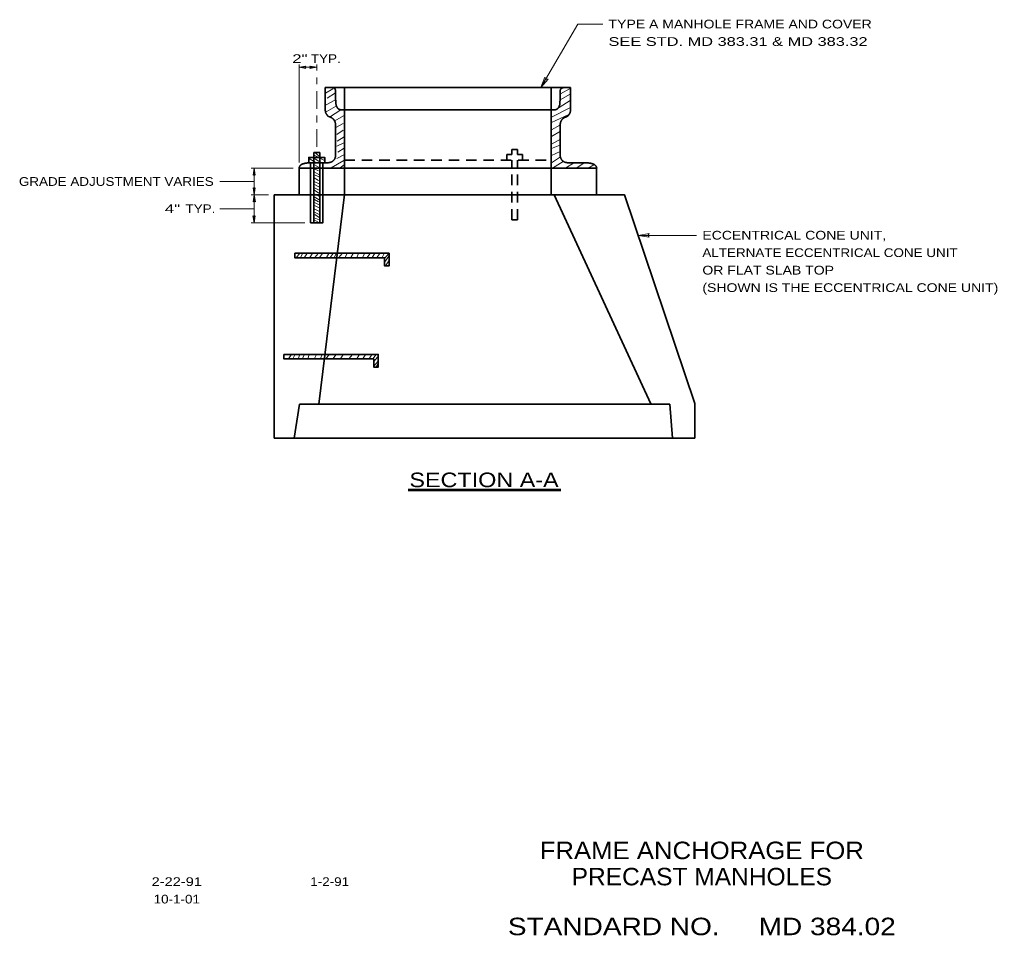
# Model space of a CAD drawing. Extents: x 21 to 35.7, y -17 to 3.5.
# Drawn here: x 21.5 to 35.74, y -17.04 to -3.71 of the extents above; entities that cross this region are included whole.
import ezdxf
from ezdxf.enums import TextEntityAlignment as Align

# ---------------------------------------------------------------- set-up
doc = ezdxf.new("R2010")
doc.units = 0
doc.header["$LTSCALE"] = 0.051
for name, pattern in [('DOT_DASHED', [7.7, 5, -1.2, 0.3, -1.2]), ('DOTTED', [1.5, 0.3, -1.2]), ('MEDIUM_DASHED', [4.5, 3, -1.5])]:
    doc.linetypes.add(name, pattern=pattern)
for name, color, linetype, lineweight in [('1', 7, 'Continuous', 35), ('10', 7, 'Continuous', 13), ('12', 7, 'Continuous', 53), ('6', 7, 'DOTTED', 13)]:
    doc.layers.add(name, color=color, linetype=linetype, lineweight=lineweight)
doc.layers.add('13', color=7, linetype='Continuous')

msp = doc.modelspace()

# ---------------------------------------------------------------- linework, layer by layer
at = {"layer": '1'}
for p, q in [((25.9515, -4.69192), (29.52275, -4.69192)), ((25.9515, -4.69192), (25.9515, -4.99533)), ((26.23083, -6.25367), (26.23083, -4.69192)), ((29.24342, -6.25367), (29.24342, -4.69192)), ((29.52275, -4.69192), (29.52275, -4.99533)), ((26.18608, -5.01858), (29.28817, -5.01858)), ((26.10133, -5.67925), (26.10133, -5.27792)), ((29.37292, -5.67925), (29.37292, -5.27792)), ((25.78383, -6.66225), (25.78383, -5.64075)), ((25.87033, -5.64075), (25.78383, -5.64075)), ((25.69417, -5.79242), (25.94292, -5.79242)), ((25.73592, -6.66225), (25.73592, -5.79283)), ((29.78008, -5.79242), (29.53133, -5.79242)), ((25.5695, -5.86875), (25.5695, -6.25517)), ((25.5695, -5.86875), (29.9025, -5.86875)), ((25.56725, -6.10233), (25.5695, -6.10192)), ((25.20825, -9.79667), (25.20825, -6.25617)), ((26.23083, -6.25367), (25.85725, -9.30125)), ((30.691, -9.296), (29.28475, -6.25458)), ((25.499, -9.79667), (25.57425, -9.305)), ((25.57425, -9.305), (30.97125, -9.30433)), ((30.97125, -9.30433), (31.00867, -9.79667)), ((31.33242, -9.79667), (31.33242, -9.293)), ((25.20825, -9.79667), (31.33242, -9.79667))]:
    msp.add_line(p, q, dxfattribs=at)
for points in [[(25.87658, -6.66225), (25.87033, -6.66225), (25.87033, -5.64075)], [(25.71125, -5.79242), (25.71125, -5.71292), (25.94292, -5.71292), (25.94292, -5.79242)], [(25.73592, -6.66225), (25.91825, -6.66225), (25.91825, -5.79458)], [(31.33058, -9.29358), (30.31017, -6.25675), (25.20825, -6.25617)]]:
    msp.add_lwpolyline(points, dxfattribs=at)
for points in [[(25.5085, -7.10775), (26.88042, -7.10775), (26.88042, -7.29117), (26.81633, -7.29117), (26.81633, -7.17167), (25.5085, -7.17167)], [(25.35058, -8.57967), (26.7225, -8.57967), (26.7225, -8.76308), (26.65842, -8.76308), (26.65842, -8.64358), (25.35058, -8.64358)]]:
    msp.add_lwpolyline(points, close=True, dxfattribs=at)
for points in [[(26.03483, -4.69192), (26.04558, -4.69433), (26.05317, -4.69575), (26.06225, -4.6975), (26.06933, -4.69942), (26.07533, -4.70158), (26.07925, -4.70342), (26.08267, -4.70533), (26.08617, -4.7075), (26.08908, -4.70992), (26.09175, -4.71275), (26.09392, -4.7155), (26.09542, -4.71842), (26.097, -4.7225), (26.09808, -4.7265), (26.09942, -4.73033), (26.10075, -4.73642), (26.102, -4.74725), (26.10225, -4.75067), (26.10225, -4.752), (26.10225, -4.75358), (26.10225, -4.75667), (26.10225, -4.76025), (26.10233, -4.76475), (26.10242, -4.76917), (26.10225, -4.774), (26.10225, -4.77742), (26.10208, -4.78208), (26.10208, -4.78383), (26.10225, -4.79117), (26.10242, -4.79633), (26.1025, -4.80042), (26.1025, -4.80867), (26.10258, -4.81925), (26.10258, -4.82783), (26.10275, -4.83442), (26.10258, -4.84308), (26.10225, -4.84958), (26.10258, -4.86658), (26.10292, -4.87717), (26.104, -4.8845), (26.1045, -4.89008), (26.10517, -4.89542), (26.10567, -4.90083), (26.1065, -4.90842), (26.10658, -4.91133), (26.10658, -4.91442), (26.10683, -4.92633), (26.10717, -4.93442), (26.10817, -4.94133), (26.11033, -4.94925), (26.11125, -4.95175), (26.11233, -4.95558), (26.11467, -4.96317), (26.11733, -4.96917), (26.119, -4.974), (26.12008, -4.978), (26.12217, -4.981), (26.12317, -4.98367), (26.12533, -4.98592), (26.12742, -4.98883), (26.1285, -4.99083), (26.13058, -4.99275), (26.13258, -4.99475), (26.13575, -4.99967), (26.13775, -5.00133), (26.13992, -5.00358), (26.14208, -5.00492), (26.14408, -5.00617), (26.14717, -5.00842), (26.14942, -5.00967), (26.15183, -5.01042), (26.15433, -5.01108), (26.15817, -5.013), (26.16042, -5.01383), (26.16217, -5.01458), (26.16567, -5.016), (26.16867, -5.01692), (26.17075, -5.01792), (26.17483, -5.01883), (26.18608, -5.01858)], [(29.43942, -4.69192), (29.42867, -4.69433), (29.42108, -4.69575), (29.412, -4.6975), (29.40492, -4.69942), (29.39892, -4.70158), (29.395, -4.70342), (29.39158, -4.70533), (29.38808, -4.7075), (29.38517, -4.70992), (29.3825, -4.71275), (29.38033, -4.7155), (29.37883, -4.71842), (29.37725, -4.7225), (29.37617, -4.7265), (29.37483, -4.73033), (29.3735, -4.73642), (29.37225, -4.74725), (29.372, -4.75067), (29.372, -4.752), (29.372, -4.75358), (29.372, -4.75667), (29.372, -4.76025), (29.37192, -4.76475), (29.37183, -4.76917), (29.372, -4.774), (29.372, -4.77742), (29.37217, -4.78208), (29.37217, -4.78383), (29.372, -4.79117), (29.37183, -4.79633), (29.37175, -4.80042), (29.37175, -4.80867), (29.37167, -4.81925), (29.37167, -4.82783), (29.3715, -4.83442), (29.37167, -4.84308), (29.372, -4.84958), (29.37167, -4.86658), (29.37133, -4.87717), (29.37025, -4.8845), (29.36975, -4.89008), (29.36908, -4.89542), (29.36858, -4.90083), (29.36775, -4.90842), (29.36767, -4.91133), (29.36767, -4.91442), (29.36742, -4.92633), (29.36708, -4.93442), (29.36608, -4.94133), (29.36392, -4.94925), (29.363, -4.95175), (29.36192, -4.95558), (29.35958, -4.96317), (29.35692, -4.96917), (29.35525, -4.974), (29.35417, -4.978), (29.35208, -4.981), (29.35108, -4.98367), (29.34892, -4.98592), (29.34683, -4.98883), (29.34575, -4.99083), (29.34367, -4.99275), (29.34167, -4.99475), (29.3385, -4.99967), (29.3365, -5.00133), (29.33433, -5.00358), (29.33217, -5.00492), (29.33017, -5.00617), (29.32708, -5.00842), (29.32483, -5.00967), (29.32242, -5.01042), (29.31992, -5.01108), (29.31608, -5.013), (29.31383, -5.01383), (29.31208, -5.01458), (29.30858, -5.016), (29.30558, -5.01692), (29.3035, -5.01792), (29.29942, -5.01883), (29.28817, -5.01858)], [(25.9515, -4.99533), (25.9515, -5.00208), (25.9515, -5.01008), (25.95117, -5.01333), (25.95183, -5.01925), (25.952, -5.03108), (25.95283, -5.03542), (25.9535, -5.04225), (25.95433, -5.046), (25.9545, -5.04833), (25.95533, -5.05117), (25.95533, -5.0525), (25.95567, -5.05383), (25.95617, -5.0555), (25.95683, -5.05783), (25.958, -5.06133), (25.95967, -5.0645), (25.96133, -5.06667), (25.96233, -5.06917), (25.9635, -5.07133), (25.96433, -5.07367), (25.96533, -5.07533), (25.96717, -5.0785), (25.96933, -5.08167), (25.9725, -5.08617), (25.97417, -5.08883), (25.97633, -5.09233), (25.979, -5.09567), (25.98067, -5.09917), (25.98392, -5.10208), (25.98625, -5.10425), (25.98825, -5.10625), (25.99125, -5.10942), (25.99542, -5.11292), (26.00158, -5.11642), (26.00742, -5.11908), (26.01342, -5.12125), (26.01892, -5.12342), (26.02225, -5.12458), (26.02533, -5.12567), (26.02658, -5.12608), (26.02833, -5.12667), (26.03742, -5.13117), (26.04108, -5.133), (26.0465, -5.13592), (26.05283, -5.14058), (26.05975, -5.14575), (26.0625, -5.14817), (26.06567, -5.151), (26.06883, -5.15417), (26.07075, -5.15633), (26.07292, -5.15892), (26.07508, -5.16133), (26.07742, -5.16475), (26.08058, -5.16883), (26.08267, -5.172), (26.08442, -5.17467), (26.08558, -5.177), (26.08758, -5.18025), (26.08925, -5.18383), (26.091, -5.18733), (26.09375, -5.194), (26.09608, -5.20083), (26.09725, -5.20508), (26.09817, -5.20858), (26.09892, -5.214), (26.09983, -5.21917), (26.10067, -5.22358), (26.10125, -5.22967), (26.10117, -5.23683), (26.10067, -5.24517), (26.10067, -5.25483), (26.10092, -5.26225), (26.10117, -5.27275), (26.10117, -5.27708), (26.10133, -5.27792)], [(29.52275, -4.99533), (29.52275, -5.00208), (29.52275, -5.01008), (29.52308, -5.01333), (29.52242, -5.01925), (29.52225, -5.03108), (29.52142, -5.03542), (29.52075, -5.04225), (29.51992, -5.046), (29.51975, -5.04833), (29.51892, -5.05117), (29.51892, -5.0525), (29.51858, -5.05383), (29.51808, -5.0555), (29.51742, -5.05783), (29.51625, -5.06133), (29.51458, -5.0645), (29.51292, -5.06667), (29.51192, -5.06917), (29.51075, -5.07133), (29.50992, -5.07367), (29.50892, -5.07533), (29.50708, -5.0785), (29.50492, -5.08167), (29.50175, -5.08617), (29.50008, -5.08883), (29.49792, -5.09233), (29.49525, -5.09567), (29.49358, -5.09917), (29.49033, -5.10208), (29.488, -5.10425), (29.486, -5.10625), (29.483, -5.10942), (29.47883, -5.11292), (29.47267, -5.11642), (29.46683, -5.11908), (29.46083, -5.12125), (29.45533, -5.12342), (29.452, -5.12458), (29.44892, -5.12567), (29.44767, -5.12608), (29.44592, -5.12667), (29.43683, -5.13117), (29.43317, -5.133), (29.42775, -5.13592), (29.42142, -5.14058), (29.4145, -5.14575), (29.41175, -5.14817), (29.40858, -5.151), (29.40542, -5.15417), (29.4035, -5.15633), (29.40133, -5.15892), (29.39917, -5.16133), (29.39683, -5.16475), (29.39367, -5.16883), (29.39158, -5.172), (29.38983, -5.17467), (29.38867, -5.177), (29.38667, -5.18025), (29.385, -5.18383), (29.38325, -5.18733), (29.3805, -5.194), (29.37817, -5.20083), (29.377, -5.20508), (29.37608, -5.20858), (29.37533, -5.214), (29.37442, -5.21917), (29.37358, -5.22358), (29.373, -5.22967), (29.37308, -5.23683), (29.37358, -5.24517), (29.37358, -5.25483), (29.37333, -5.26225), (29.37308, -5.27275), (29.37308, -5.27708), (29.37292, -5.27792)], [(26.10133, -5.67925), (26.10158, -5.68442), (26.10108, -5.69167), (26.10067, -5.698), (26.09833, -5.70783), (26.09692, -5.71292), (26.09558, -5.71733), (26.094, -5.72242), (26.091, -5.72892), (26.08767, -5.73558), (26.08192, -5.74425), (26.07717, -5.75025), (26.07075, -5.75725), (26.0655, -5.76183), (26.05933, -5.76692), (26.05075, -5.77233), (26.04475, -5.77567), (26.03933, -5.77883), (26.03267, -5.78125), (26.02933, -5.78217), (26.02517, -5.78358), (26.01992, -5.78517), (26.01625, -5.78583), (26.01358, -5.786), (26.00958, -5.78708), (26.00533, -5.78758), (26.00083, -5.78825), (25.99667, -5.78933), (25.99208, -5.7895), (25.98825, -5.78983), (25.98475, -5.79042), (25.98092, -5.79058), (25.97617, -5.79092), (25.97225, -5.79133), (25.96858, -5.79217), (25.96442, -5.79233), (25.95875, -5.79233), (25.95275, -5.7925), (25.94825, -5.7925), (25.94292, -5.79242)], [(29.37292, -5.67925), (29.37267, -5.68442), (29.37317, -5.69167), (29.37358, -5.698), (29.37592, -5.70783), (29.37733, -5.71292), (29.37867, -5.71733), (29.38025, -5.72242), (29.38325, -5.72892), (29.38658, -5.73558), (29.39233, -5.74425), (29.39708, -5.75025), (29.4035, -5.75725), (29.40875, -5.76183), (29.41492, -5.76692), (29.4235, -5.77233), (29.4295, -5.77567), (29.43492, -5.77883), (29.44158, -5.78125), (29.44492, -5.78217), (29.44908, -5.78358), (29.45433, -5.78517), (29.458, -5.78583), (29.46067, -5.786), (29.46467, -5.78708), (29.46892, -5.78758), (29.47342, -5.78825), (29.47758, -5.78933), (29.48217, -5.7895), (29.486, -5.78983), (29.4895, -5.79042), (29.49333, -5.79058), (29.49808, -5.79092), (29.502, -5.79133), (29.50567, -5.79217), (29.50983, -5.79233), (29.5155, -5.79233), (29.5215, -5.7925), (29.526, -5.7925), (29.53133, -5.79242)], [(25.69417, -5.79242), (25.6915, -5.7925), (25.68492, -5.79342), (25.67808, -5.79442), (25.66517, -5.79608), (25.65858, -5.79717), (25.65358, -5.798), (25.64792, -5.79908), (25.64492, -5.8), (25.64258, -5.801), (25.63917, -5.80225), (25.63617, -5.80292), (25.63392, -5.8035), (25.63208, -5.80417), (25.62925, -5.80475), (25.62683, -5.80558), (25.62375, -5.80658), (25.62017, -5.80725), (25.61675, -5.80858), (25.61358, -5.80975), (25.61083, -5.81142), (25.60867, -5.81258), (25.60633, -5.81367), (25.60292, -5.8155), (25.60075, -5.81767), (25.598, -5.81942), (25.59608, -5.82092), (25.59475, -5.82225), (25.59192, -5.82542), (25.58892, -5.82792), (25.58642, -5.8305), (25.58017, -5.83867), (25.57667, -5.84475), (25.57483, -5.84917), (25.57358, -5.85308), (25.57242, -5.85708), (25.57108, -5.86158), (25.5695, -5.86875)], [(29.78008, -5.79242), (29.78275, -5.7925), (29.78933, -5.79342), (29.79617, -5.79442), (29.80908, -5.79608), (29.81567, -5.79717), (29.82067, -5.798), (29.82633, -5.79908), (29.82933, -5.8), (29.83167, -5.801), (29.83508, -5.80225), (29.83808, -5.80292), (29.84033, -5.8035), (29.84217, -5.80417), (29.845, -5.80475), (29.84742, -5.80558), (29.8505, -5.80658), (29.85408, -5.80725), (29.8575, -5.80858), (29.86067, -5.80975), (29.86342, -5.81142), (29.86558, -5.81258), (29.86792, -5.81367), (29.87133, -5.8155), (29.8735, -5.81767), (29.87625, -5.81942), (29.87817, -5.82092), (29.8795, -5.82225), (29.88233, -5.82542), (29.88533, -5.82792), (29.88783, -5.8305), (29.89408, -5.83867), (29.89758, -5.84475), (29.89942, -5.84917), (29.90067, -5.85308), (29.90183, -5.85708), (29.90317, -5.86158), (29.90475, -5.86875)]]:
    msp.add_spline(points, degree=3, dxfattribs=at)
at = {"layer": '10'}
for p, q in [((29.0925, -4.69642), (29.62708, -3.77083)), ((29.62708, -3.77083), (29.99283, -3.77083)), ((25.5695, -5.78542), (25.5695, -4.35858)), ((25.66933, -4.3825), (25.5695, -4.40025)), ((25.66967, -4.41583), (25.5695, -4.40025)), ((25.5695, -4.40025), (25.82708, -4.40025)), ((25.66933, -4.3825), (25.657, -4.39933)), ((25.66967, -4.41583), (25.657, -4.39933)), ((25.72692, -4.38467), (25.82708, -4.40025)), ((25.72692, -4.38467), (25.73958, -4.40117)), ((25.72725, -4.418), (25.82708, -4.40025)), ((25.72725, -4.418), (25.73958, -4.40117)), ((29.14942, -4.5445), (29.0925, -4.69642)), ((29.14942, -4.5445), (29.1625, -4.57517)), ((29.19558, -4.57117), (29.0925, -4.69642)), ((29.19558, -4.57117), (29.1625, -4.57517)), ((25.48617, -5.86875), (24.87492, -5.86875)), ((24.89992, -5.96875), (24.91658, -5.86875)), ((24.89992, -5.96875), (24.91658, -5.95625)), ((24.93325, -5.96875), (24.91658, -5.86875)), ((24.91658, -6.25617), (24.91658, -5.86875)), ((24.93325, -5.96875), (24.91658, -5.95625)), ((24.91658, -6.0625), (24.41658, -6.0625)), ((25.12492, -6.25617), (24.87492, -6.25617)), ((24.89992, -6.15617), (24.91658, -6.25617)), ((24.89992, -6.15617), (24.91658, -6.16867)), ((24.90133, -6.35642), (24.91658, -6.25617)), ((24.93325, -6.15617), (24.91658, -6.25617)), ((24.93325, -6.15617), (24.91658, -6.16867)), ((24.93467, -6.35592), (24.91658, -6.25617)), ((24.91658, -6.25617), (24.91658, -6.66225)), ((24.90133, -6.35642), (24.91783, -6.34367)), ((24.93467, -6.35592), (24.91783, -6.34367)), ((24.91658, -6.45917), (24.41658, -6.45917)), ((25.65258, -6.66225), (24.87492, -6.66225)), ((24.8985, -6.5625), (24.91658, -6.66225)), ((24.8985, -6.5625), (24.91533, -6.57475)), ((24.93183, -6.562), (24.91533, -6.57475)), ((24.93183, -6.562), (24.91658, -6.66225)), ((30.66817, -6.81908), (30.50825, -6.84617)), ((30.66817, -6.81908), (30.64825, -6.84583)), ((30.66833, -6.87242), (30.50825, -6.84617)), ((30.50825, -6.84617), (31.3595, -6.84617)), ((30.66833, -6.87242), (30.64825, -6.84583))]:
    msp.add_line(p, q, dxfattribs=at)
at = {"layer": '10', "linetype": 'DOT_DASHED'}
msp.add_line((25.82708, -5.55742), (25.82708, -4.35858), dxfattribs=at)
at = {"layer": '10', "linetype": 'MEDIUM_DASHED', "lineweight": 35}
for p, q in [((28.59383, -5.75042), (28.59383, -5.67092)), ((28.59383, -5.67092), (28.66642, -5.67092)), ((28.75292, -5.59875), (28.66642, -5.59875)), ((28.66642, -5.67092), (28.66642, -5.59875)), ((28.75292, -5.67092), (28.75292, -5.59875)), ((28.75292, -5.67092), (28.8255, -5.67092)), ((28.8255, -5.67092), (28.8255, -5.75042)), ((26.23083, -5.75042), (29.24342, -5.75042)), ((28.66642, -6.62025), (28.66642, -5.75042)), ((28.75292, -6.62025), (28.75292, -5.75042)), ((28.66642, -6.62025), (28.75292, -6.62025))]:
    msp.add_line(p, q, dxfattribs=at)
at = {"layer": '10', "lineweight": 35}
msp.add_line((29.9025, -5.86875), (29.9025, -6.25675), dxfattribs=at)
at = {"layer": '12'}
msp.add_line((27.15758, -10.5505), (29.38308, -10.5505), dxfattribs=at)
at = {"layer": '6', "linetype": 'Continuous'}
for p, q in [((25.95417, -4.77767), (26.05992, -4.71567)), ((26.10175, -4.77275), (25.977, -4.85008)), ((29.37242, -4.875), (29.5175, -4.79225)), ((29.51892, -4.70833), (29.37517, -4.7885)), ((26.09158, -4.87775), (25.96367, -4.94725)), ((25.96667, -5.049), (26.10258, -4.97033)), ((29.24575, -5.12767), (29.52233, -4.98283)), ((29.51975, -4.88275), (29.356, -4.98517)), ((26.16483, -5.029), (26.02908, -5.11567)), ((26.09042, -5.17825), (26.21725, -5.10483)), ((29.49892, -5.08767), (29.24792, -5.20133)), ((26.21442, -5.21667), (26.11667, -5.27058)), ((29.24658, -5.30817), (29.36842, -5.24)), ((26.11883, -5.37742), (26.21433, -5.3145)), ((29.37742, -5.33025), (29.2475, -5.4055)), ((26.11908, -5.54708), (26.23008, -5.49292)), ((26.22642, -5.41417), (26.12475, -5.47408)), ((29.36567, -5.53208), (29.24617, -5.58308)), ((29.24792, -5.51825), (29.37767, -5.446)), ((25.7885, -5.67708), (25.93883, -5.759)), ((25.8, -5.64092), (25.86825, -5.69783)), ((26.12058, -5.72675), (26.22242, -5.67175)), ((26.22558, -5.57692), (26.13417, -5.63767)), ((29.24783, -5.68275), (29.372, -5.62383)), ((25.71517, -5.72733), (25.81758, -5.78875)), ((25.78642, -5.724), (25.89725, -5.78908)), ((25.79442, -5.81767), (25.86142, -5.85733)), ((26.03675, -5.86125), (26.22, -5.75567)), ((26.22733, -5.82042), (26.16708, -5.86258)), ((29.37867, -5.70358), (29.24592, -5.78933)), ((29.26142, -5.86725), (29.41575, -5.77225)), ((29.45625, -5.86575), (29.56775, -5.795)), ((29.606, -5.86867), (29.718, -5.79525)), ((29.77908, -5.86817), (29.86392, -5.81892)), ((25.78225, -5.87483), (25.85317, -5.90642)), ((25.78608, -5.96258), (25.85808, -5.99608)), ((25.78933, -5.92358), (25.85733, -5.96017)), ((25.788, -6.00842), (25.85392, -6.04608)), ((25.793, -6.10517), (25.85783, -6.13783)), ((25.80033, -6.06508), (25.861, -6.09492)), ((25.79258, -6.188), (25.85975, -6.23367)), ((25.795, -6.153), (25.86292, -6.18667)), ((25.79675, -6.24283), (25.85958, -6.27758)), ((25.79158, -6.28783), (25.86158, -6.32742)), ((25.79417, -6.36867), (25.86417, -6.40425)), ((25.79433, -6.32575), (25.85508, -6.3585)), ((25.79508, -6.41258), (25.862, -6.44717)), ((25.79592, -6.50633), (25.86383, -6.541)), ((25.79875, -6.54425), (25.86267, -6.58492)), ((25.80117, -6.46433), (25.85992, -6.49517)), ((25.788, -6.61833), (25.86008, -6.65983)), ((25.7895, -6.59133), (25.86342, -6.61983)), ((25.52608, -7.17233), (25.57975, -7.10742)), ((25.59025, -7.17008), (25.62567, -7.1075)), ((25.64525, -7.171), (25.6845, -7.113)), ((25.72783, -7.17042), (25.75958, -7.11267)), ((25.80183, -7.16933), (25.84875, -7.10925)), ((25.8655, -7.16967), (25.91075, -7.1105)), ((25.96967, -7.17042), (26.00292, -7.1125)), ((26.02333, -7.16817), (26.06775, -7.11)), ((26.07925, -7.16975), (26.11033, -7.11358)), ((26.15092, -7.16842), (26.19583, -7.11133)), ((26.24183, -7.168), (26.26675, -7.11325)), ((26.32383, -7.16767), (26.35817, -7.11183)), ((26.40925, -7.16842), (26.43617, -7.11183)), ((26.4915, -7.16983), (26.52283, -7.11342)), ((26.56325, -7.16892), (26.60025, -7.11342)), ((26.63242, -7.169), (26.66958, -7.11275)), ((26.70075, -7.169), (26.74392, -7.11042)), ((26.78075, -7.16808), (26.80875, -7.11142)), ((26.819, -7.17617), (26.87525, -7.10917)), ((26.81975, -7.2315), (26.87725, -7.14842)), ((26.8305, -7.28925), (26.87667, -7.21925)), ((25.415, -8.64117), (25.45342, -8.58308)), ((25.47992, -8.64125), (25.50642, -8.58408)), ((25.55667, -8.64125), (25.58192, -8.58183)), ((25.616, -8.64117), (25.64983, -8.58217)), ((25.69617, -8.64175), (25.71925, -8.58083)), ((25.7955, -8.64083), (25.82633, -8.58142)), ((25.88133, -8.64075), (25.90817, -8.58)), ((25.95383, -8.642), (26.01192, -8.58083)), ((26.06133, -8.64108), (26.10908, -8.58092)), ((26.17133, -8.64108), (26.21408, -8.58017)), ((26.296, -8.64475), (26.34925, -8.57925)), ((26.41208, -8.64258), (26.44758, -8.583)), ((26.49817, -8.641), (26.53933, -8.58125)), ((26.5905, -8.641), (26.63067, -8.581)), ((26.64233, -8.64242), (26.691, -8.58133)), ((26.65942, -8.68275), (26.71417, -8.61875)), ((26.66025, -8.75042), (26.72033, -8.67558)), ((26.691, -8.76067), (26.71925, -8.7195))]:
    msp.add_line(p, q, dxfattribs=at)

# ---------------------------------------------------------------- texts
at = {"layer": '12'}
for s, width, p in [('TYPE A MANHOLE FRAME AND COVER', 1.2, (30.07608, -3.83442)), ('SEE STD. MD 383.31 & MD 383.32', 1.4, (30.07608, -4.08875)), ('GRADE ADJUSTMENT VARIES', 1.15, (21.49033, -6.12608)), ('4"', 1.45, (23.61425, -6.52275)), ('TYP.', 1.15, (23.9165, -6.52275)), ('ECCENTRICAL CONE UNIT,', 1.2, (31.44275, -6.90758)), ('ALTERNATE ECCENTRICAL CONE UNIT', 1.15, (31.44275, -7.16192)), ('OR FLAT SLAB TOP', 1.2, (31.44275, -7.41625)), ('(SHOWN IS THE ECCENTRICAL CONE UNIT)', 1.2, (31.44275, -7.67058))]:
    msp.add_text(s, height=0.1272, dxfattribs=dict(at, width=width)).set_placement(p)
for s, height, width, p in [('TYP.', 0.1272, 1.15, (25.95958, -4.33775)), ('SECTION A-A', 0.212, 1.2, (28.26325, -10.51108))]:
    msp.add_text(s, height=height, dxfattribs=dict(at, width=width)).set_placement(p, align=Align.CENTER)
at = {"layer": '13'}
for s, height, width, p in [('2"', 0.1272, 1.45, (25.58212, -4.33775)), ('FRAME ANCHORAGE FOR', 0.2544, 1.1, (31.43454, -15.92492)), ('PRECAST MANHOLES', 0.2544, 1.05, (31.43454, -16.3065)), ('2-22-91', 0.1272, 1.25, (23.7895, -16.3165)), ('1-2-91', 0.1272, 1.15, (26.01583, -16.3165)), ('10-1-01', 0.1272, 1.15, (23.7895, -16.57083)), ('STANDARD NO.     MD 384.02', 0.2544, 1.2, (31.43454, -17.03208))]:
    msp.add_text(s, height=height, dxfattribs=dict(at, width=width)).set_placement(p, align=Align.CENTER)

doc.saveas('drawing.dxf')
